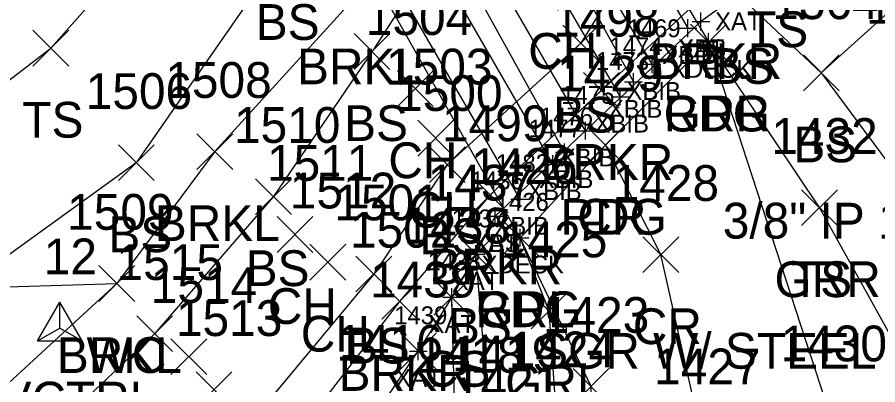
# Model space of a CAD drawing. Extents: x 1441651 to 1442140, y 243798 to 245625.
# Drawn here: x 1442027.42 to 1442075.54, y 245384.36 to 245404.9 of the extents above; entities that cross this region are included whole.
import ezdxf

# ---------------------------------------------------------------- set-up
doc = ezdxf.new("R2010")
doc.units = 0
for name, color, linetype in [('B_A', 7, 'Continuous'), ('B_I', 7, 'Continuous'), ('B_TIC', 7, 'Continuous'), ('BB', 7, 'Continuous'), ('BELB', 7, 'Continuous'), ('BSE', 7, 'Continuous'), ('BSUBM', 7, 'Continuous'), ('C_A', 7, 'Continuous'), ('C_I', 7, 'Continuous'), ('CPSM', 7, 'Continuous'), ('L_A', 7, 'Continuous'), ('L_I', 7, 'Continuous'), ('L_TIC', 7, 'Continuous'), ('LAWE', 7, 'Continuous'), ('LELB', 7, 'Continuous'), ('M_C', 7, 'Continuous'), ('M_I', 7, 'Continuous'), ('P_A', 7, 'Continuous'), ('P_I', 7, 'Continuous'), ('P_TIC', 7, 'Continuous'), ('PEU', 7, 'Continuous'), ('PRC', 7, 'Continuous'), ('R_A', 7, 'Continuous'), ('R_C', 7, 'Continuous'), ('R_I', 7, 'Continuous'), ('R_TIC', 7, 'Continuous'), ('RGR', 7, 'Continuous')]:
    doc.layers.add(name, color=color, linetype=linetype)

msp = doc.modelspace()

# ---------------------------------------------------------------- linework, layer by layer
at = {"layer": 'B_TIC'}
for p, q in [((1442065.655, 245404.659), (1442065.73, 245404.659)), ((1442065.655, 245404.659), (1442065.73, 245404.659)), ((1442064.921, 245404.29), (1442064.997, 245404.29)), ((1442066.079, 245403.514), (1442066.155, 245403.514)), ((1442062.918, 245402.28), (1442062.994, 245402.28)), ((1442061.88, 245401.279), (1442061.956, 245401.279)), ((1442061.131, 245400.457), (1442061.206, 245400.457)), ((1442059.191, 245398.559), (1442059.266, 245398.559)), ((1442058.02, 245397.352), (1442058.096, 245397.352)), ((1442057.37, 245396.683), (1442057.446, 245396.683)), ((1442055.531, 245394.741), (1442055.607, 245394.741)), ((1442054.155, 245393.78), (1442054.23, 245393.78)), ((1442054.155, 245393.78), (1442054.23, 245393.78)), ((1442055.549, 245392.581), (1442055.625, 245392.581)), ((1442053.075, 245391.658), (1442053.15, 245391.658)), ((1442051.721, 245389.254), (1442051.796, 245389.254)), ((1442049.853, 245386.244), (1442049.929, 245386.244))]:
    msp.add_line(p, q, dxfattribs=at)
for points in [[(1442065.651, 245404.159), (1442065.651, 245405.159)], [(1442065.651, 245404.159), (1442065.651, 245405.159)], [(1442064.918, 245403.79), (1442064.918, 245404.79)], [(1442065.151, 245404.659), (1442066.151, 245404.659)], [(1442065.151, 245404.659), (1442066.151, 245404.659)], [(1442064.418, 245404.29), (1442065.418, 245404.29)], [(1442066.076, 245403.014), (1442066.076, 245404.014)], [(1442065.576, 245403.514), (1442066.576, 245403.514)], [(1442062.915, 245401.78), (1442062.915, 245402.78)], [(1442062.415, 245402.28), (1442063.415, 245402.28)], [(1442061.877, 245400.779), (1442061.877, 245401.779)], [(1442061.377, 245401.279), (1442062.377, 245401.279)], [(1442061.127, 245399.957), (1442061.127, 245400.957)], [(1442060.627, 245400.457), (1442061.627, 245400.457)], [(1442059.188, 245398.059), (1442059.188, 245399.059)], [(1442058.688, 245398.559), (1442059.688, 245398.559)], [(1442058.017, 245396.852), (1442058.017, 245397.852)], [(1442057.517, 245397.352), (1442058.517, 245397.352)], [(1442057.367, 245396.183), (1442057.367, 245397.183)], [(1442056.867, 245396.683), (1442057.867, 245396.683)], [(1442055.528, 245394.241), (1442055.528, 245395.241)], [(1442055.028, 245394.741), (1442056.028, 245394.741)], [(1442054.151, 245393.28), (1442054.151, 245394.28)], [(1442054.151, 245393.28), (1442054.151, 245394.28)], [(1442053.651, 245393.78), (1442054.651, 245393.78)], [(1442053.651, 245393.78), (1442054.651, 245393.78)], [(1442055.546, 245392.081), (1442055.546, 245393.081)], [(1442055.046, 245392.581), (1442056.046, 245392.581)], [(1442053.071, 245391.158), (1442053.071, 245392.158)], [(1442052.571, 245391.658), (1442053.571, 245391.658)], [(1442051.717, 245388.754), (1442051.717, 245389.754)], [(1442051.217, 245389.254), (1442052.217, 245389.254)], [(1442049.85, 245385.744), (1442049.85, 245386.744)], [(1442049.35, 245386.244), (1442050.35, 245386.244)]]:
    msp.add_lwpolyline(points, dxfattribs=at)
at = {"layer": 'BB'}
for points in [[(1442053.99, 245422.959), (1442064.918, 245404.29)], [(1442062.915, 245402.28), (1442052.057, 245421.088)], [(1442051.357, 245420.4), (1442061.877, 245401.279)], [(1442050.186, 245419.229), (1442061.127, 245400.457)], [(1442059.188, 245398.559), (1442048.316, 245417.358)], [(1442058.017, 245397.352), (1442047.446, 245416.472)], [(1442057.367, 245396.683), (1442046.483, 245415.511)], [(1442044.627, 245413.558), (1442055.528, 245394.741)]]:
    msp.add_lwpolyline(points, dxfattribs=at)
at = {"layer": 'BELB'}
for points in [[(1442053.641, 245424.38), (1442066.076, 245403.514)], [(1442043.134, 245414.629), (1442055.546, 245392.581)]]:
    msp.add_lwpolyline(points, dxfattribs=at)
at = {"layer": 'BSE'}
msp.add_lwpolyline([(1442065.651, 245404.659), (1442054.151, 245393.78)], dxfattribs=at)
at = {"layer": 'BSUBM'}
for points in [[(1442069.82, 245408.225), (1442067.737, 245406.173), (1442065.651, 245404.659)], [(1442054.151, 245393.78), (1442053.071, 245391.658), (1442051.717, 245389.254), (1442049.85, 245386.244)]]:
    msp.add_lwpolyline(points, dxfattribs=at)
at = {"layer": 'CPSM'}
for p, q in [((1442028.559, 245386.813), (1442029.809, 245388.978)), ((1442031.059, 245386.813), (1442029.809, 245388.978)), ((1442029.81, 245387.534), (1442029.809, 245388.978)), ((1442028.559, 245386.813), (1442029.81, 245387.534)), ((1442029.81, 245387.534), (1442029.81, 245387.534)), ((1442029.81, 245387.534), (1442031.059, 245386.813)), ((1442028.559, 245386.813), (1442031.059, 245386.813))]:
    msp.add_line(p, q, dxfattribs=at)
at = {"layer": 'L_TIC'}
for points in [[(1442057.938, 245402.451), (1442059.938, 245404.451)], [(1442059.938, 245402.451), (1442057.938, 245404.451)], [(1442028.302, 245402.168), (1442030.302, 245404.168)], [(1442030.302, 245402.168), (1442028.302, 245404.168)], [(1442046.261, 245401.979), (1442048.261, 245403.979)], [(1442048.261, 245401.979), (1442046.261, 245403.979)], [(1442071.375, 245400.791), (1442073.375, 245402.791)], [(1442073.375, 245400.791), (1442071.375, 245402.791)], [(1442071.375, 245400.791), (1442073.375, 245402.791)], [(1442073.375, 245400.791), (1442071.375, 245402.791)], [(1442048.686, 245399.904), (1442050.686, 245401.904)], [(1442050.686, 245399.904), (1442048.686, 245401.904)], [(1442059.085, 245399.813), (1442061.085, 245401.813)], [(1442061.085, 245399.813), (1442059.085, 245401.813)], [(1442049.818, 245397.139), (1442051.818, 245399.139)], [(1442051.818, 245397.139), (1442049.818, 245399.139)], [(1442037.474, 245396.39), (1442039.474, 245398.39)], [(1442039.474, 245396.39), (1442037.474, 245398.39)], [(1442033.081, 245395.771), (1442035.081, 245397.771)], [(1442035.081, 245395.771), (1442033.081, 245397.771)], [(1442050.468, 245395.66), (1442052.468, 245397.66)], [(1442052.468, 245395.66), (1442050.468, 245397.66)], [(1442040.756, 245393.877), (1442042.756, 245395.877)], [(1442042.756, 245393.877), (1442040.756, 245395.877)], [(1442052.875, 245393.968), (1442054.875, 245395.968)], [(1442054.875, 245393.968), (1442052.875, 245395.968)], [(1442071.276, 245393.261), (1442073.276, 245395.261)], [(1442073.276, 245393.261), (1442071.276, 245395.261)], [(1442041.949, 245391.76), (1442043.949, 245393.76)], [(1442043.949, 245391.76), (1442041.949, 245393.76)], [(1442052.071, 245390.658), (1442054.071, 245392.658)], [(1442054.071, 245390.658), (1442052.071, 245392.658)], [(1442043.792, 245390.214), (1442045.792, 245392.214)], [(1442045.792, 245390.214), (1442043.792, 245392.214)], [(1442046.361, 245389.552), (1442048.361, 245391.552)], [(1442048.361, 245389.552), (1442046.361, 245391.552)], [(1442031.995, 245389.022), (1442033.995, 245391.022)], [(1442033.995, 245389.022), (1442031.995, 245391.022)], [(1442031.995, 245389.022), (1442033.995, 245391.022)], [(1442033.995, 245389.022), (1442031.995, 245391.022)], [(1442047.801, 245388.024), (1442049.801, 245390.024)], [(1442049.801, 245388.024), (1442047.801, 245390.024)], [(1442050.717, 245388.254), (1442052.717, 245390.254)], [(1442052.717, 245388.254), (1442050.717, 245390.254)], [(1442034.105, 245386.217), (1442036.105, 245388.217)], [(1442036.105, 245386.217), (1442034.105, 245388.217)], [(1442048.85, 245385.244), (1442050.85, 245387.244)], [(1442050.85, 245385.244), (1442048.85, 245387.244)], [(1442036.02, 245384.934), (1442038.02, 245386.934)], [(1442038.02, 245384.934), (1442036.02, 245386.934)], [(1442037.424, 245383.087), (1442039.424, 245385.087)], [(1442039.424, 245383.087), (1442037.424, 245385.087)]]:
    msp.add_lwpolyline(points, dxfattribs=at)
at = {"layer": 'LAWE'}
for points in [[(1441911.342, 245568.336), (1441913.54, 245547.368), (1441930.794, 245525.129), (1441943.112, 245500.641), (1441948.928, 245491.303), (1441946.177, 245479.068), (1441949.055, 245463.199), (1441952.693, 245455.284), (1441960.253, 245454.331), (1441970.926, 245435.223), (1441995.301, 245411.435), (1442005.916, 245405.86), (1442024.361, 245389.769), (1442032.995, 245390.022)], [(1442099.331, 245492.7), (1442082.175, 245474.825), (1442073.962, 245459.556), (1442071.044, 245454.669), (1442067.5, 245447.08), (1442064.769, 245439.016), (1442060.82, 245433.995), (1442057.711, 245424.573), (1442056.016, 245422.421), (1442050.947, 245416.77), (1442046.422, 245406.149), (1442038.474, 245397.39), (1442032.995, 245390.022), (1442022.028, 245379.959), (1442015.438, 245373.014), (1442011.82, 245364.946), (1441999.311, 245341.928), (1441993.277, 245326.588), (1441983.696, 245301.797)], [(1442108.799, 245476.467), (1442096.827, 245461.697), (1442085.936, 245448.636), (1442079.446, 245435.792), (1442078.126, 245432.436), (1442074.215, 245419.929), (1442069.905, 245412.33), (1442066.174, 245406.441), (1442060.085, 245400.813), (1442053.875, 245394.968), (1442048.801, 245389.024), (1442033.753, 245369.5), (1442027.295, 245353.918), (1442016.143, 245332.931), (1442008.363, 245317.18), (1442000.261, 245295.499)]]:
    msp.add_lwpolyline(points, dxfattribs=at)
at = {"layer": 'LELB'}
for points in [[(1441923.447, 245583.224), (1441912.774, 245568.104), (1441914.394, 245547.708), (1441930.794, 245525.129), (1441946.539, 245502.48), (1441950.678, 245491.319), (1441947.348, 245479.457), (1441950.826, 245463.211), (1441954.445, 245457.195), (1441962.212, 245455.423), (1441972.577, 245437.756), (1441995.951, 245413.456), (1442007.462, 245408.084), (1442021.352, 245397.079), (1442029.302, 245403.168), (1442035.632, 245410.326), (1442039.926, 245412.912), (1442042.785, 245414.272)], [(1442102.458, 245487.565), (1442084.345, 245473.245), (1442077.162, 245458.74), (1442072.716, 245452.8), (1442069.733, 245445.651), (1442066.867, 245437.139), (1442063.415, 245431.599), (1442060.353, 245422.411), (1442058.711, 245418.726), (1442054.414, 245414.049), (1442047.261, 245402.979), (1442041.756, 245394.877), (1442035.105, 245387.217), (1442025.138, 245377.826), (1442014.243, 245362.921), (1442001.678, 245340.269), (1441995.167, 245325.255), (1441985.519, 245301.167)], [(1442107.479, 245478.045), (1442095.111, 245463.136), (1442085.124, 245450.231), (1442079.931, 245439.38), (1442074.016, 245430.6), (1442072.192, 245422.421), (1442067.602, 245415.77), (1442063.525, 245410.875), (1442058.938, 245403.451), (1442051.468, 245396.66), (1442047.361, 245390.552), (1442031.625, 245371.637), (1442024.894, 245355.937), (1442013.328, 245334.791), (1442005.478, 245318.663), (1441997.832, 245296.612)], [(1442128.7, 245453.168), (1442114.47, 245439.461), (1442106.293, 245436.041), (1442091.133, 245416.249), (1442087.362, 245410.975), (1442078.918, 245407.703), (1442072.375, 245401.791), (1442078.662, 245393.315), (1442088.165, 245379.007), (1442078.347, 245359.722), (1442066.466, 245343.929), (1442051.618, 245313.899)], [(1442042.32, 245408.629), (1442034.081, 245396.771), (1442024.361, 245389.769)], [(1442067.737, 245406.173), (1442072.375, 245401.791)], [(1442066.466, 245343.929), (1442078.106, 245383.773), (1442072.276, 245394.261)], [(1442052.21, 245373.013), (1442053.865, 245382.108), (1442053.071, 245391.658)], [(1442052.17, 245365.322), (1442052.21, 245373.013), (1442051.913, 245382.032), (1442051.717, 245389.254)], [(1442037.743, 245368.514), (1442047.447, 245382.708), (1442049.85, 245386.244)]]:
    msp.add_lwpolyline(points, dxfattribs=at)
at = {"layer": 'P_TIC'}
for points in [[(1442065.076, 245402.514), (1442067.076, 245404.514)], [(1442067.076, 245402.514), (1442065.076, 245404.514)], [(1442065.076, 245402.514), (1442067.076, 245404.514)], [(1442067.076, 245402.514), (1442065.076, 245404.514)], [(1442059.308, 245396.749), (1442061.308, 245398.749)], [(1442061.308, 245396.749), (1442059.308, 245398.749)], [(1442059.308, 245396.749), (1442061.308, 245398.749)], [(1442061.308, 245396.749), (1442059.308, 245398.749)], [(1442054.546, 245391.581), (1442056.546, 245393.581)], [(1442056.546, 245391.581), (1442054.546, 245393.581)], [(1442062.407, 245390.635), (1442064.407, 245392.635)], [(1442064.407, 245390.635), (1442062.407, 245392.635)], [(1442058.506, 245383.265), (1442060.506, 245385.265)], [(1442060.506, 245383.265), (1442058.506, 245385.265)]]:
    msp.add_lwpolyline(points, dxfattribs=at)
at = {"layer": 'PEU'}
for points in [[(1442021.575, 245270.007), (1442029.759, 245297.223), (1442038.899, 245320.233), (1442046.726, 245342.734), (1442056.785, 245360.956), (1442059.331, 245377.916), (1442059.506, 245384.265), (1442055.546, 245392.581), (1442060.308, 245397.749), (1442066.076, 245403.514)], [(1442035.638, 245264.666), (1442045.154, 245291.534), (1442051.618, 245313.899), (1442059.292, 245334.8), (1442069.056, 245356.182), (1442072.881, 245382.672), (1442066.076, 245403.514)]]:
    msp.add_lwpolyline(points, dxfattribs=at)
at = {"layer": 'PRC'}
msp.add_lwpolyline([(1442028.667, 245266.9), (1442037.624, 245294.471), (1442044.859, 245317.347), (1442051.821, 245337.799), (1442063.019, 245359.496), (1442065.727, 245381.387), (1442063.407, 245391.635), (1442060.308, 245397.749)], dxfattribs=at)
at = {"layer": 'R_TIC'}
for points in [[(1442065.076, 245402.514), (1442067.076, 245404.514)], [(1442067.076, 245402.514), (1442065.076, 245404.514)], [(1442071.276, 245393.261), (1442073.276, 245395.261)], [(1442073.276, 245393.261), (1442071.276, 245395.261)], [(1442054.546, 245391.581), (1442056.546, 245393.581)], [(1442056.546, 245391.581), (1442054.546, 245393.581)], [(1442056.162, 245387.485), (1442058.162, 245389.485)], [(1442058.162, 245387.485), (1442056.162, 245389.485)]]:
    msp.add_lwpolyline(points, dxfattribs=at)
at = {"layer": 'RGR'}
for points in [[(1442072.276, 245394.261), (1442066.076, 245403.514)], [(1442057.592, 245382.339), (1442057.162, 245388.485), (1442055.546, 245392.581)]]:
    msp.add_lwpolyline(points, dxfattribs=at)

# ---------------------------------------------------------------- texts
at = {"layer": 'B_A'}
for s, p in [('XAT', (1442066.442, 245404.173)), ('XAT', (1442064.356, 245402.659)), ('XBS', (1442064.391, 245402.659)), ('XBIB', (1442063.489, 245402.29)), ('XDECK', (1442063.918, 245401.514)), ('XBIB', (1442061.486, 245400.28)), ('XBIB', (1442060.448, 245399.279)), ('XBIB', (1442059.698, 245398.457)), ('XBIB', (1442057.758, 245396.559)), ('XBIB', (1442056.588, 245395.352)), ('XBIB', (1442055.938, 245394.683)), ('XBIB', (1442054.099, 245392.741)), ('XAT', (1442052.856, 245391.78)), ('XBS', (1442052.891, 245391.78)), ('XDECK', (1442053.388, 245390.581)), ('XAT', (1442051.776, 245389.658)), ('XAT', (1442050.422, 245387.254)), ('XAT', (1442048.554, 245384.244))]:
    msp.add_text(s, height=1, dxfattribs=at).set_placement(p)
at = {"layer": 'B_I'}
for s, p in [('1469', (1442061.541, 245403.78)), ('1474', (1442060.53, 245402.779)), ('1473', (1442059.781, 245401.957)), ('1475', (1442057.841, 245400.059)), ('1476', (1442056.643, 245398.852)), ('1477', (1442056.02, 245398.183)), ('1482', (1442054.181, 245396.241)), ('1436', (1442052.777, 245395.28)), ('1436', (1442052.777, 245395.28)), ('1426', (1442054.172, 245394.081)), ('1437', (1442051.725, 245393.158)), ('1438', (1442050.371, 245390.754)), ('1439', (1442048.499, 245387.744))]:
    msp.add_text(s, height=1, dxfattribs=at).set_placement(p)
at = {"layer": 'C_A'}
msp.add_text('HVCTRL', height=2, dxfattribs=at).set_placement((1442024.503, 245382.534))
at = {"layer": 'C_I'}
msp.add_text('12', height=2, dxfattribs=at).set_placement((1442028.912, 245390.534))
at = {"layer": 'L_A'}
for s, p in [('BS', (1442040.761, 245403.629)), ('TS', (1442068.229, 245403.225)), ('CH', (1442055.996, 245402.016)), ('BRKL', (1442043.068, 245401.149)), ('BRKR', (1442062.765, 245401.441)), ('BS', (1442066.178, 245401.173)), ('TS', (1442027.711, 245398.168)), ('BS', (1442057.379, 245398.451)), ('BS', (1442045.702, 245397.979)), ('BS', (1442070.816, 245396.791)), ('BS', (1442070.816, 245396.791)), ('CH', (1442048.174, 245395.904)), ('BRKR', (1442056.675, 245395.813)), ('CH', (1442049.306, 245393.139)), ('BRKL', (1442035.12, 245392.39)), ('BS', (1442032.522, 245391.771)), ('BS', (1442049.908, 245391.66)), ('BS', (1442040.197, 245389.877)), ('BRKR', (1442050.465, 245389.968)), ('TS', (1442070.685, 245389.261)), ('CH', (1442041.437, 245387.76)), ('BS', (1442051.512, 245386.658)), ('CH', (1442043.28, 245386.214)), ('BS', (1442045.802, 245385.552)), ('BRKL', (1442029.641, 245385.022)), ('WC', (1442031.302, 245385.022)), ('CS', (1442050.158, 245384.254)), ('BRKR', (1442045.392, 245384.024))]:
    msp.add_text(s, height=2, dxfattribs=at).set_placement(p)
at = {"layer": 'L_I'}
for s, p in [('1364', (1442069.635, 245404.791)), ('1364', (1442069.635, 245404.791)), ('1504', (1442046.914, 245403.904)), ('1498', (1442057.392, 245403.813)), ('1503', (1442048.046, 245401.139)), ('1508', (1442035.702, 245400.39)), ('1506', (1442031.255, 245399.771)), ('1500', (1442048.609, 245399.66)), ('1510', (1442039.544, 245397.877)), ('1499', (1442051.174, 245397.968)), ('1432', (1442069.583, 245397.261)), ('1511', (1442041.39, 245395.76)), ('1512', (1442042.666, 245394.214)), ('1437', (1442050.378, 245394.658)), ('1501', (1442045.157, 245393.552)), ('1509', (1442030.216, 245393.022)), ('1509', (1442030.216, 245393.022)), ('1502', (1442046.03, 245392.024)), ('1438', (1442049.024, 245392.254)), ('1515', (1442032.979, 245390.217)), ('1439', (1442047.149, 245389.244)), ('1514', (1442034.894, 245388.934)), ('1513', (1442036.298, 245387.087)), ('1416', (1442045.266, 245385.708)), ('1416', (1442045.266, 245385.708)), ('1419', (1442051.731, 245385.108)), ('1424', (1442054.899, 245385.339)), ('1418', (1442049.787, 245385.032)), ('1421', (1442051.841, 245383.476))]:
    msp.add_text(s, height=2, dxfattribs=at).set_placement(p)
at = {"layer": 'M_C'}
msp.add_text('3/8" IP 12" AGS', height=2, dxfattribs=at).set_placement((1442066.872, 245392.531))
at = {"layer": 'M_I'}
msp.add_text('1434', height=2, dxfattribs=at).set_placement((1442074.887, 245404.531))
at = {"layer": 'P_A'}
for s, p in [('RDG', (1442063.564, 245398.514)), ('RDG', (1442063.564, 245398.514)), ('RDG', (1442057.796, 245392.749)), ('CR', (1442058.741, 245392.749)), ('RDG', (1442053.034, 245387.581)), ('CR', (1442061.84, 245386.635))]:
    msp.add_text(s, height=2, dxfattribs=at).set_placement(p)
at = {"layer": 'P_I'}
for s, p in [('1429', (1442057.607, 245400.749)), ('1429', (1442057.607, 245400.749)), ('1426', (1442052.798, 245395.581)), ('1428', (1442060.714, 245394.635)), ('1423', (1442056.813, 245387.265)), ('1430', (1442070.102, 245385.672)), ('1427', (1442063.034, 245384.387))]:
    msp.add_text(s, height=2, dxfattribs=at).set_placement(p)
at = {"layer": 'R_A'}
for s, p in [('GRR', (1442063.564, 245398.514)), ('GRR', (1442069.764, 245389.261)), ('GRL', (1442053.089, 245387.581)), ('GRL', (1442054.705, 245383.485))]:
    msp.add_text(s, height=2, dxfattribs=at).set_placement(p)
at = {"layer": 'R_C'}
msp.add_text('SGR W/ STEEL POST', height=2, dxfattribs=at).set_placement((1442056.441, 245385.261))
at = {"layer": 'R_I'}
for s, p in [('1432', (1442069.583, 245397.261)), ('1426', (1442052.798, 245395.581)), ('1425', (1442054.469, 245391.485)), ('1424', (1442054.899, 245385.339))]:
    msp.add_text(s, height=2, dxfattribs=at).set_placement(p)

doc.saveas('drawing.dxf')
